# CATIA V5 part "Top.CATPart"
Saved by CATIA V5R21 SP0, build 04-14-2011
Part number: Part1.1
Bounding box of the stored display mesh (mm): x -50 to 50, y -25 to 25, z -20 to 10
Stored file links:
  D:\CATIA V5R21 E-RESOURCES\CATIA-V5R21\catia-v5r21-Prts\c12_catia_v5r21_prt\c12_catia_v5r21figr_12-22\Top.CATPart
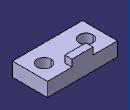
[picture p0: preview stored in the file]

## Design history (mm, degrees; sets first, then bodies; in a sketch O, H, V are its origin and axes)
Body1 (main body)
  Sketch1 on xy-plane, origin (0, 0, 0), H (1, 0, 0), V (0, 1, 0)
    line L1 (50, 25) -> (50, -25)
    line L2 (50, -25) -> (-50, -25)
    line L3 (-50, -25) -> (-50, 25)
    line L4 (-50, 25) -> (50, 25)
    circle A1 centre (-30, 0) radius 10
    point P5 (-30, 0)
    circle A2 centre (30, 0) radius 10
    length L2 = 100
    length L1 = 50
    radius A1 = 10
    distance P5 V = 30
    vertical: L1 V, L3 V
    horizontal: L2 H, L4 H
    equidistance: L1 L3 O, L2 L4 O
    coincidence: P5 H
    symmetry: A1 A2 V
  Pad1: profile Sketch1, direction (0, 0, -1), length 20
  Sketch2 on face of Pad1, origin (0, 0, 0), H (1, 0, 0), V (0, 1, 0)
    line L1 (-15, 25) -> (15, 25)
    line L2 (15, 25) -> (15, 15)
    line L3 (15, 15) -> (-15, 15)
    line L4 (-15, 15) -> (-15, 25)
    reference projected line E1 (50, 25) -> (-50, 25) from edge [face of Pad1 | face of Pad1]
    length L1 = 30
    distance L4 V = 15
    length L2 = 10
    horizontal: L1 H, L3 H
    vertical: L2 V, L4 V
    coincidence: L1 E1
  Pad2: profile Sketch2, direction (0, 0, 1), length 10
